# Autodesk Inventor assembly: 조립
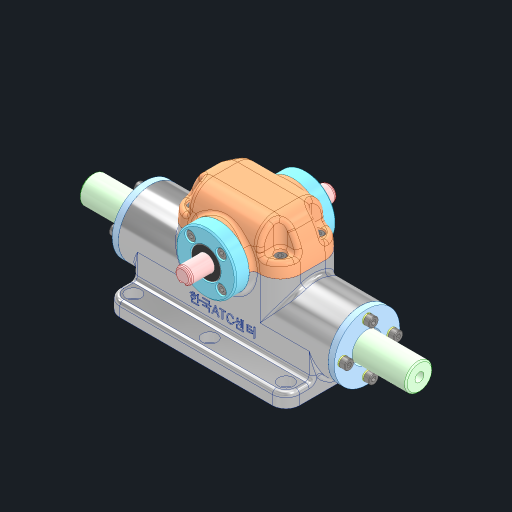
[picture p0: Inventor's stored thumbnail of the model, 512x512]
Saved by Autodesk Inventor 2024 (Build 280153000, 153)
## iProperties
Created: 2024-06
Part Number: 조립
Document SubType Name: Assembly
Designer: kh_501
Author: kh_501
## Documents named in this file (13)
- C:\Users\kh_501\Desktop\740604V1007\조립.iam
- C:\Users\kh_501\Desktop\740604V1007\본체.ipt
- C:\Users\kh_501\Desktop\740604V1007\깊은 홈 볼 베어링 6901\깊은 홈 볼 베어링 6901.ipt
- C:\Users\kh_501\Desktop\740604V1007\랙\랙.ipt
- C:\Users\kh_501\Desktop\740604V1007\베어링 커버\베어링 커버.ipt
- C:\Users\kh_501\Desktop\740604V1007\부시 커버\부시 커버.ipt
- C:\Users\kh_501\Desktop\740604V1007\스프링 와셔 M4\스프링 와셔 M4.ipt
- C:\Users\kh_501\Desktop\740604V1007\오일레스 부시\오일레스 부시.ipt
- C:\Users\kh_501\Desktop\740604V1007\오일실 12 22 7\오일실 12 22 7.ipt
- C:\Users\kh_501\Desktop\740604V1007\윗커버\윗커버.ipt
- C:\Users\kh_501\Desktop\740604V1007\육각 소켓 머리 볼트 M4x10\육각 소켓 머리 볼트 M4x10.ipt
- C:\Users\kh_501\Desktop\740604V1007\칼라\칼라.ipt
- C:\Users\kh_501\Desktop\740604V1007\피니언\피니언.ipt
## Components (1 placed, 1 different names)
1. 피니언:1 — 각도:8, 각도:10, 각도:14
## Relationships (3: Angle 3)
- 각도:8 [Angle]: 피니언:1
- 각도:10 [Angle]: 피니언:1
- 각도:14 [Angle]: 피니언:1
